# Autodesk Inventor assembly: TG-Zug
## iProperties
Shininess: 20.0
Angle Display Precision: 2
Document Length Units: 11269
Document Angle Units: 11279
Document Time Units: 11290
Document Mass Units: 11283
Document Length Units Precision: 3
Document Angle Units Precision: 2
Created: 2003-04
Part Number: TG-Zug
Document SubType Name: Baugruppe
Designer: Administrator
Density: 0.0
Volumn: 0.0
Area: 0.0
PropertySet Name: Model Information
Control State: 0
Master: False
Checked Out: False
Author: Administrator
